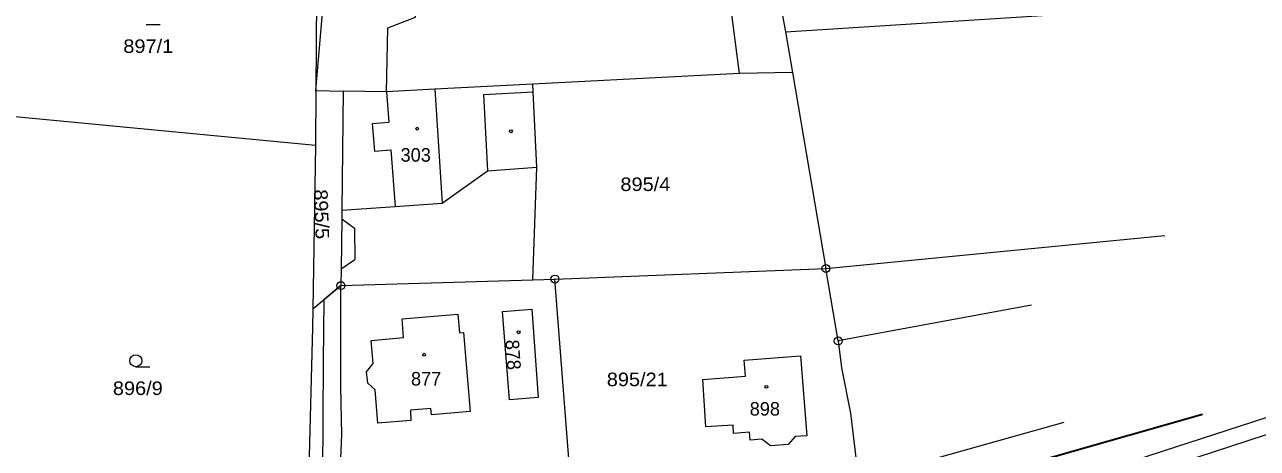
# Model space of a CAD drawing. Extents: x -686207 to -681951, y -1020493 to -1017811.
# Drawn here: x -682433.3 to -682278.7, y -1019073.2 to -1019020.1 of the extents above; entities that cross this region are included whole.
import ezdxf

# ---------------------------------------------------------------- set-up
doc = ezdxf.new("R2010")
doc.units = 0
doc.header["$LTSCALE"] = 0.4
for name, color, linetype, lineweight in [('1', 7, 'Continuous', 13), ('13', 7, 'Continuous', 13), ('3', 7, 'Continuous', 13), ('4', 7, 'Continuous', 13), ('45', 7, 'Continuous', 35), ('5', 7, 'Continuous', 13), ('8', 7, 'Continuous', 13)]:
    doc.layers.add(name, color=color, linetype=linetype, lineweight=lineweight)
doc.layers.add('2', color=7, linetype='Continuous')

msp = doc.modelspace()

# ---------------------------------------------------------------- linework, layer by layer
at = {"layer": '1'}
for p, q in [((-682396.64, -1019009.02), (-682396.76, -1019028.35)), ((-682337.89, -1019021), (-682287.95, -1019017.83)), ((-682343.65, -1019026.23), (-682369.57, -1019027.55)), ((-682337.02, -1019026.08), (-682332.81, -1019050.68)), ((-682396.76, -1019028.35), (-682396.8, -1019035.27)), ((-682396.76, -1019028.35), (-682393.34, -1019028.42)), ((-682393.34, -1019028.42), (-682393.5, -1019043.37)), ((-682387.9, -1019028.52), (-682393.34, -1019028.42)), ((-682396.8, -1019035.27), (-682440.72, -1019031.07)), ((-682396.8, -1019035.27), (-682397.15, -1019055.72)), ((-682331.26, -1019059.77), (-682332.81, -1019050.68)), ((-682364.62, -1019080), (-682366.78, -1019052.01)), ((-682397.15, -1019055.72), (-682393.61, -1019052.83)), ((-682307.04, -1019055.27), (-682331.26, -1019059.77)), ((-682302.99, -1019070), (-682328.73, -1019077.2))]:
    msp.add_line(p, q, dxfattribs=at)
for points in [[(-682343.65, -1019026.23), (-682348.28, -1018990.46), (-682354.3, -1018976.07)], [(-682342.94, -1018993.38), (-682337.89, -1019021), (-682337.02, -1019026.08), (-682343.65, -1019026.23)], [(-682387.9, -1019028.52), (-682387.75, -1019020.5), (-682384.26, -1019019.14), (-682384.4, -1019014.03), (-682386.34, -1019011.27), (-682387.24, -1019008.31), (-682387.56, -1019004.85)], [(-682393.5, -1019043.37), (-682386.8, -1019042.89), (-682380.9, -1019042.47), (-682375.22, -1019038.42), (-682369.05, -1019037.96), (-682369.53, -1019028.52), (-682369.57, -1019027.55)], [(-682369.57, -1019027.55), (-682381.84, -1019028.17), (-682387.9, -1019028.52)], [(-682393.5, -1019043.37), (-682393.51, -1019044.45), (-682393.57, -1019050.71), (-682393.61, -1019052.83)], [(-682366.78, -1019052.01), (-682332.81, -1019050.68), (-682290.31, -1019046.53)], [(-682393.61, -1019052.83), (-682369.55, -1019052.12), (-682366.78, -1019052.01)], [(-682393.97, -1019082.28), (-682393.49, -1019071.55), (-682393.62, -1019065.56), (-682393.61, -1019052.83)], [(-682397.15, -1019055.72), (-682397.19, -1019058.1), (-682398.25, -1019099.97)], [(-682331.26, -1019059.77), (-682330.85, -1019063.15), (-682329.75, -1019068.81), (-682328.73, -1019077.2)]]:
    msp.add_lwpolyline(points, dxfattribs=at)
for points in [[(-682385.75, -1019059.34), (-682385.94, -1019057.01), (-682378.96, -1019056.4), (-682378.75, -1019058.76), (-682378.23, -1019058.72), (-682377.39, -1019068.62), (-682382.26, -1019069.05), (-682382.33, -1019068.24), (-682384.91, -1019068.45), (-682384.83, -1019069.73), (-682388.97, -1019070.08), (-682389.31, -1019065.88), (-682390.23, -1019065.07), (-682390.39, -1019063.65), (-682389.59, -1019062.61), (-682389.82, -1019059.71)], [(-682368.89, -1019066.84), (-682372.5, -1019067.15), (-682373.34, -1019056.09), (-682369.68, -1019055.8)], [(-682344.46, -1019070.35), (-682347.86, -1019070.56), (-682348.23, -1019064.59), (-682342.88, -1019064.18), (-682343.04, -1019062.19), (-682336.01, -1019061.64), (-682335.2, -1019071.67), (-682336.68, -1019071.76), (-682337.56, -1019072.76), (-682339.75, -1019072.94), (-682340.86, -1019072.08), (-682342.31, -1019072.21), (-682342.4, -1019071.2), (-682344.38, -1019071.37)]]:
    msp.add_lwpolyline(points, close=True, dxfattribs=at)
at = {"layer": '13'}
for points in [[(-682393.97, -1019082.28), (-682393.49, -1019071.55), (-682393.62, -1019065.56), (-682393.61, -1019052.83), (-682395.77, -1019054.59), (-682395.82, -1019062.34), (-682396, -1019090.76)], [(-682263.24, -1019064.72), (-682288.98, -1019073.11), (-682301.07, -1019077.01)], [(-682288.46, -1019075.05), (-682262.6, -1019066.62)]]:
    msp.add_lwpolyline(points, dxfattribs=at)
at = {"layer": '3'}
for p, q in [((-682418.013, -1019020.09), (-682416.263, -1019020.09)), ((-682419.323, -1019063), (-682417.573, -1019063))]:
    msp.add_line(p, q, dxfattribs=at)
msp.add_circle((-682419.3229, -1019062.2498), 0.75, dxfattribs=at)
at = {"layer": '4'}
for p, q in [((-682396.76, -1019028.35), (-682393.12, -1018986.59)), ((-682387.9, -1019028.52), (-682387.61, -1019032.32)), ((-682381.84, -1019028.17), (-682380.9, -1019042.47)), ((-682375.72, -1019028.85), (-682369.53, -1019028.52)), ((-682375.72, -1019028.85), (-682375.22, -1019038.42)), ((-682389.69, -1019032.48), (-682387.61, -1019032.32)), ((-682389.69, -1019032.48), (-682389.42, -1019035.96)), ((-682389.42, -1019035.96), (-682387.35, -1019035.8)), ((-682387.35, -1019035.8), (-682386.8, -1019042.89)), ((-682369.55, -1019052.12), (-682369.05, -1019037.96)), ((-682393.51, -1019044.45), (-682391.91, -1019045.61)), ((-682391.91, -1019045.61), (-682391.89, -1019049.56)), ((-682393.57, -1019050.71), (-682391.89, -1019049.56))]:
    msp.add_line(p, q, dxfattribs=at)
at = {"layer": '45'}
msp.add_line((-682327.552, -1019080.892), (-682285.616, -1019068.942), dxfattribs=at)
at = {"layer": '5'}
for centre in [(-682384.0468, -1019033.1392), (-682372.2968, -1019033.4692), (-682371.3368, -1019058.6792), (-682383.1868, -1019061.4892), (-682340.2768, -1019065.5192)]:
    msp.add_circle(centre, 0.175, dxfattribs=at)
at = {"layer": '8'}
for centre, radius in [((-682332.81, -1019050.6799), 0.5), ((-682332.81, -1019050.6799), 0.0303), ((-682366.78, -1019052.0099), 0.5), ((-682366.78, -1019052.0099), 0.0303), ((-682393.61, -1019052.8299), 0.5), ((-682393.61, -1019052.8299), 0.0303), ((-682331.26, -1019059.7699), 0.5), ((-682331.26, -1019059.7699), 0.0303)]:
    msp.add_circle(centre, radius, dxfattribs=at)

# ---------------------------------------------------------------- texts
at = {"layer": '2', "width": 1.1}
for s, p in [('897/1', (-682420.893, -1019023.64)), ('895/4', (-682358.573, -1019040.96)), ('895/21', (-682360.285, -1019065.44)), ('896/9', (-682422.203, -1019066.549))]:
    msp.add_text(s, height=1.7, dxfattribs=at).set_placement(p)
at = {"layer": '2'}
for s, p in [('303', (-682386.134, -1019037.28)), ('877', (-682384.83, -1019065.36)), ('898', (-682342.364, -1019069.13))]:
    msp.add_text(s, height=1.7, dxfattribs=at).set_placement(p)
at = {"layer": '2', "width": 1.1}
msp.add_text('895/5', height=1.7, rotation=272, dxfattribs=at).set_placement((-682396.996, -1019040.777))
at = {"layer": '2'}
msp.add_text('878', height=1.7, rotation=274, dxfattribs=at).set_placement((-682372.997, -1019059.669))

doc.saveas('drawing.dxf')
